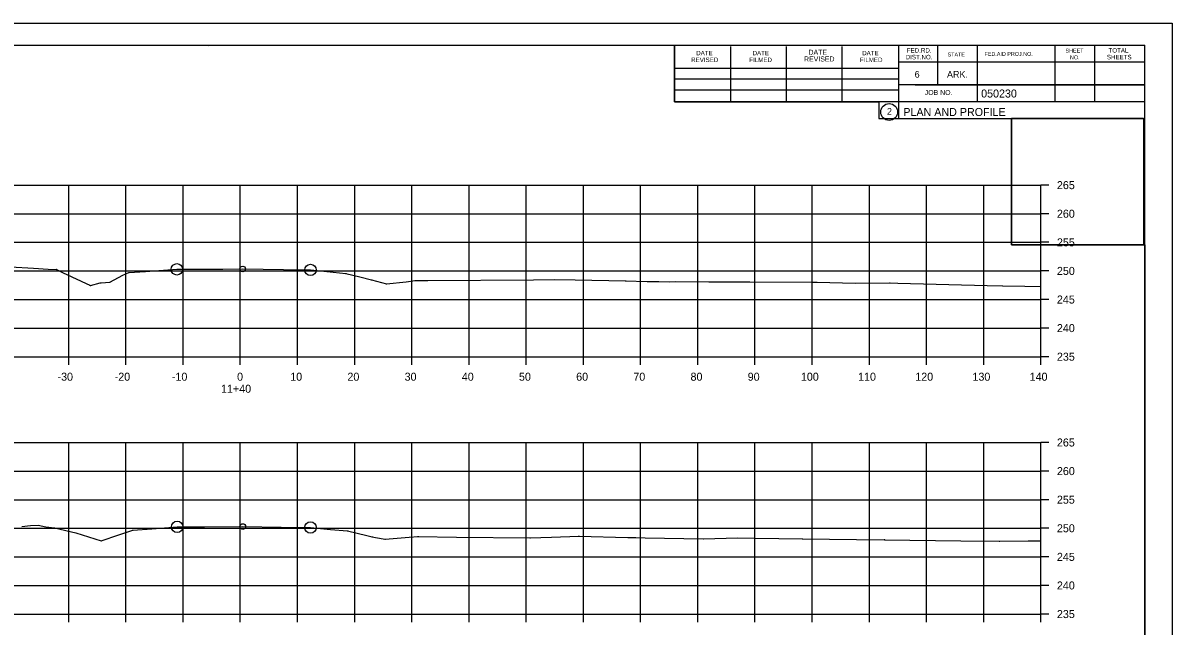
# Model space of a CAD drawing. Extents: x 1300404 to 1323571, y 234004 to 252077.
# Drawn here: x 1315679.3 to 1315880.2, y 243729.7 to 243835.2 of the extents above; entities that cross this region are included whole.
import ezdxf

# ---------------------------------------------------------------- set-up
doc = ezdxf.new("R2010")
doc.units = 0
for name, color, linetype in [('Default', 7, 'Continuous'), ('R_Axis', 7, 'Continuous'), ('R_Axis Annot', 7, 'Continuous'), ('R_Border', 7, 'Continuous'), ('R_Border Prem', 7, 'Continuous'), ('R_Draft', 7, 'Continuous'), ('R_Exist Surface', 7, 'Continuous'), ('R_Grid', 7, 'Continuous'), ('R_No Plot', 7, 'Continuous')]:
    doc.layers.add(name, color=color, linetype=linetype)

msp = doc.modelspace()

# ---------------------------------------------------------------- linework, layer by layer
at = {"layer": 'Default'}
for p, q in [((1315559.28, 243831.27), (1315875.46, 243831.27)), ((1315793.2, 243821.39), (1315793.2, 243831.27)), ((1315803.06, 243821.39), (1315803.06, 243831.07)), ((1315812.82, 243821.39), (1315812.82, 243831.07)), ((1315822.5, 243821.39), (1315822.5, 243831.07)), ((1315832.36, 243831.27), (1315832.36, 243818.47)), ((1315839.2, 243831.27), (1315839.2, 243824.33)), ((1315846.14, 243831.27), (1315846.14, 243821.39)), ((1315859.72, 243831.27), (1315859.72, 243821.39)), ((1315866.66, 243831.27), (1315866.66, 243821.39)), ((1315875.46, 243625.81), (1315875.46, 243831.27)), ((1315793.2, 243827.25), (1315832.36, 243827.25)), ((1315875.46, 243828.33), (1315832.36, 243828.33)), ((1315875.46, 243828.35), (1315875.46, 243828.35)), ((1315793.2, 243825.39), (1315832.36, 243825.39)), ((1315793.2, 243821.39), (1315793.2, 243823.45)), ((1315793.2, 243823.45), (1315832.36, 243823.45)), ((1315875.46, 243824.33), (1315832.36, 243824.33)), ((1315835.32, 243824.33), (1315875.46, 243824.33)), ((1315875.46, 243821.39), (1315793.2, 243821.39)), ((1315832.36, 243818.47), (1315875.46, 243818.47))]:
    msp.add_line(p, q, dxfattribs=at)
msp.add_circle((1315830.74, 243819.6), 1.47, dxfattribs=at)
at = {"layer": 'R_Axis'}
for p, q in [((1315857.28, 243776.81), (1315857.28, 243806.81)), ((1315858.68, 243806.81), (1315857.28, 243806.81)), ((1315858.68, 243801.81), (1315857.28, 243801.81)), ((1315858.68, 243796.81), (1315857.28, 243796.81)), ((1315858.68, 243791.81), (1315857.28, 243791.81)), ((1315858.68, 243786.81), (1315857.28, 243786.81)), ((1315858.68, 243781.81), (1315857.28, 243781.81)), ((1315577.28, 243776.81), (1315857.28, 243776.81)), ((1315687.28, 243775.41), (1315687.28, 243776.81)), ((1315697.28, 243775.41), (1315697.28, 243776.81)), ((1315707.28, 243775.41), (1315707.28, 243776.81)), ((1315717.28, 243775.41), (1315717.28, 243776.81)), ((1315727.28, 243775.41), (1315727.28, 243776.81)), ((1315737.28, 243775.41), (1315737.28, 243776.81)), ((1315747.28, 243775.41), (1315747.28, 243776.81)), ((1315757.28, 243775.41), (1315757.28, 243776.81)), ((1315767.28, 243775.41), (1315767.28, 243776.81)), ((1315777.28, 243775.41), (1315777.28, 243776.81)), ((1315787.28, 243775.41), (1315787.28, 243776.81)), ((1315797.28, 243775.41), (1315797.28, 243776.81)), ((1315807.28, 243775.41), (1315807.28, 243776.81)), ((1315817.28, 243775.41), (1315817.28, 243776.81)), ((1315827.28, 243775.41), (1315827.28, 243776.81)), ((1315837.28, 243775.41), (1315837.28, 243776.81)), ((1315847.28, 243775.41), (1315847.28, 243776.81)), ((1315857.28, 243775.41), (1315857.28, 243776.81)), ((1315858.68, 243776.81), (1315857.28, 243776.81)), ((1315857.28, 243731.81), (1315857.28, 243761.81)), ((1315858.68, 243761.81), (1315857.28, 243761.81)), ((1315858.68, 243756.81), (1315857.28, 243756.81)), ((1315858.68, 243751.81), (1315857.28, 243751.81)), ((1315858.68, 243746.81), (1315857.28, 243746.81)), ((1315858.68, 243741.81), (1315857.28, 243741.81)), ((1315858.68, 243736.81), (1315857.28, 243736.81)), ((1315577.28, 243731.81), (1315857.28, 243731.81)), ((1315687.28, 243730.41), (1315687.28, 243731.81)), ((1315697.28, 243730.41), (1315697.28, 243731.81)), ((1315707.28, 243730.41), (1315707.28, 243731.81)), ((1315717.28, 243730.41), (1315717.28, 243731.81)), ((1315727.28, 243730.41), (1315727.28, 243731.81)), ((1315737.28, 243730.41), (1315737.28, 243731.81)), ((1315747.28, 243730.41), (1315747.28, 243731.81)), ((1315757.28, 243730.41), (1315757.28, 243731.81)), ((1315767.28, 243730.41), (1315767.28, 243731.81)), ((1315777.28, 243730.41), (1315777.28, 243731.81)), ((1315787.28, 243730.41), (1315787.28, 243731.81)), ((1315797.28, 243730.41), (1315797.28, 243731.81)), ((1315807.28, 243730.41), (1315807.28, 243731.81)), ((1315817.28, 243730.41), (1315817.28, 243731.81)), ((1315827.28, 243730.41), (1315827.28, 243731.81)), ((1315837.28, 243730.41), (1315837.28, 243731.81)), ((1315847.28, 243730.41), (1315847.28, 243731.81)), ((1315857.28, 243730.41), (1315857.28, 243731.81)), ((1315858.68, 243731.81), (1315857.28, 243731.81))]:
    msp.add_line(p, q, dxfattribs=at)
at = {"layer": 'R_Border'}
msp.add_line((1315711.8, 243831.01), (1315711.8, 243831.01), dxfattribs=at)
msp.add_line((1315711.8, 243831.01), (1315711.8, 243831.01), dxfattribs=at)
at = {"layer": 'R_Draft'}
for points in [[(1315685.11, 243792.13), (1315685.16, 243792.03), (1315685.06, 243792.03)], [(1315697.77, 243791.56), (1315697.82, 243791.46), (1315697.72, 243791.46)], [(1315735.72, 243791.41), (1315735.77, 243791.31), (1315735.67, 243791.31)], [(1315691.07, 243789.3), (1315691.12, 243789.2), (1315691.02, 243789.2)], [(1315692.91, 243789.78), (1315692.96, 243789.68), (1315692.86, 243789.68)], [(1315694.46, 243789.87), (1315694.51, 243789.77), (1315694.41, 243789.77)], [(1315740.19, 243790.29), (1315740.24, 243790.19), (1315740.14, 243790.19)], [(1315742.85, 243789.62), (1315742.9, 243789.52), (1315742.8, 243789.52)], [(1315747.85, 243790.16), (1315747.9, 243790.06), (1315747.8, 243790.06)], [(1315784.64, 243790.13), (1315784.69, 243790.03), (1315784.59, 243790.03)], [(1315817.25, 243789.92), (1315817.3, 243789.82), (1315817.2, 243789.82)], [(1315830.88, 243789.75), (1315830.93, 243789.65), (1315830.83, 243789.65)], [(1315850.59, 243789.23), (1315850.64, 243789.13), (1315850.54, 243789.13)], [(1315684.81, 243746.91), (1315684.86, 243746.81), (1315684.76, 243746.81)], [(1315698.5, 243746.52), (1315698.55, 243746.42), (1315698.45, 243746.42)], [(1315692.97, 243744.66), (1315693.02, 243744.56), (1315692.92, 243744.56)], [(1315736.01, 243746.41), (1315736.06, 243746.31), (1315735.96, 243746.31)], [(1315740.34, 243745.38), (1315740.39, 243745.28), (1315740.29, 243745.28)], [(1315742.61, 243744.93), (1315742.66, 243744.83), (1315742.56, 243744.83)], [(1315748.39, 243745.41), (1315748.44, 243745.31), (1315748.34, 243745.31)], [(1315767.96, 243745.17), (1315768.01, 243745.07), (1315767.91, 243745.07)], [(1315776.48, 243745.47), (1315776.53, 243745.37), (1315776.43, 243745.37)], [(1315786.34, 243745.23), (1315786.39, 243745.13), (1315786.29, 243745.13)], [(1315798.24, 243745.03), (1315798.29, 243744.93), (1315798.19, 243744.93)], [(1315815.6, 243744.99), (1315815.65, 243744.89), (1315815.55, 243744.89)], [(1315829.93, 243744.86), (1315829.98, 243744.76), (1315829.88, 243744.76)], [(1315850.02, 243744.59), (1315850.07, 243744.49), (1315849.97, 243744.49)]]:
    msp.add_lwpolyline(points, close=True, dxfattribs=at)
at = {"layer": 'R_Exist Surface'}
for points in [[(1315673.02, 243792.77), (1315681.09, 243792.3), (1315683.68, 243792.14), (1315685.11, 243792.08), (1315686.16, 243791.52), (1315691.07, 243789.25), (1315692.79, 243789.71), (1315692.91, 243789.73), (1315692.93, 243789.73), (1315694.46, 243789.82), (1315696.74, 243791.06), (1315697.77, 243791.51), (1315700.72, 243791.71), (1315706.19, 243792.09), (1315714.22, 243792.13), (1315717.69, 243792.15), (1315724.82, 243792.04), (1315729.55, 243791.98), (1315731.3, 243791.81), (1315735.72, 243791.36), (1315738.15, 243790.78), (1315740.19, 243790.24), (1315741.97, 243789.8), (1315742.85, 243789.57), (1315746.29, 243789.93), (1315747.85, 243790.11), (1315748.23, 243790.13), (1315748.56, 243790.14), (1315750.08, 243790.13), (1315768.56, 243790.24), (1315772.19, 243790.31), (1315775.82, 243790.26), (1315784.64, 243790.08), (1315788.41, 243789.97), (1315789.57, 243789.96), (1315790.49, 243789.96), (1315792.4, 243789.91), (1315793.39, 243789.95), (1315799.22, 243789.9), (1315803.38, 243789.9), (1315803.41, 243789.9), (1315803.44, 243789.9), (1315806.37, 243789.89), (1315817.25, 243789.87), (1315818.16, 243789.85), (1315824.79, 243789.66), (1315830.88, 243789.7), (1315832.28, 243789.67), (1315847.91, 243789.28), (1315850.59, 243789.18), (1315854.47, 243789.13), (1315857.28, 243789.11)], [(1315679.09, 243747.14), (1315680.59, 243747.29), (1315681.94, 243747.33), (1315683.25, 243747.04), (1315684.81, 243746.86), (1315688.54, 243746.02), (1315692.97, 243744.61), (1315696.03, 243745.64), (1315698.5, 243746.47), (1315701.82, 243746.73), (1315706.23, 243747.05), (1315711.04, 243747.08), (1315717.71, 243747.1), (1315724.42, 243747.01), (1315729.55, 243746.94), (1315733.04, 243746.61), (1315736.01, 243746.36), (1315739.42, 243745.54), (1315740.34, 243745.33), (1315740.91, 243745.2), (1315742.61, 243744.88), (1315746.79, 243745.24), (1315748.39, 243745.36), (1315755.1, 243745.24), (1315767.96, 243745.12), (1315771.7, 243745.25), (1315776.48, 243745.42), (1315785.02, 243745.21), (1315786.34, 243745.18), (1315788.08, 243745.16), (1315798.24, 243744.98), (1315804.27, 243745.11), (1315807.33, 243745.09), (1315815.6, 243744.94), (1315825.02, 243744.87), (1315829.93, 243744.81), (1315843.27, 243744.62), (1315850.02, 243744.54), (1315855.03, 243744.59), (1315857.28, 243744.59)]]:
    msp.add_lwpolyline(points, dxfattribs=at)
at = {"layer": 'R_Grid'}
for p, q in [((1315577.28, 243806.81), (1315857.28, 243806.81)), ((1315687.28, 243776.81), (1315687.28, 243806.81)), ((1315697.28, 243776.81), (1315697.28, 243806.81)), ((1315707.28, 243776.81), (1315707.28, 243806.81)), ((1315717.28, 243776.81), (1315717.28, 243806.81)), ((1315727.28, 243776.81), (1315727.28, 243806.81)), ((1315737.28, 243776.81), (1315737.28, 243806.81)), ((1315747.28, 243776.81), (1315747.28, 243806.81)), ((1315757.28, 243776.81), (1315757.28, 243806.81)), ((1315767.28, 243776.81), (1315767.28, 243806.81)), ((1315777.28, 243776.81), (1315777.28, 243806.81)), ((1315787.28, 243776.81), (1315787.28, 243806.81)), ((1315797.28, 243776.81), (1315797.28, 243806.81)), ((1315807.28, 243776.81), (1315807.28, 243806.81)), ((1315817.28, 243776.81), (1315817.28, 243806.81)), ((1315827.28, 243776.81), (1315827.28, 243806.81)), ((1315837.28, 243776.81), (1315837.28, 243806.81)), ((1315847.28, 243776.81), (1315847.28, 243806.81)), ((1315857.28, 243776.81), (1315857.28, 243806.81)), ((1315577.28, 243801.81), (1315857.28, 243801.81)), ((1315577.28, 243796.81), (1315857.28, 243796.81)), ((1315577.28, 243791.81), (1315857.28, 243791.81)), ((1315577.28, 243786.81), (1315857.28, 243786.81)), ((1315577.28, 243781.81), (1315857.28, 243781.81)), ((1315577.28, 243776.81), (1315857.28, 243776.81)), ((1315577.28, 243761.81), (1315857.28, 243761.81)), ((1315687.28, 243731.81), (1315687.28, 243761.81)), ((1315697.28, 243731.81), (1315697.28, 243761.81)), ((1315707.28, 243731.81), (1315707.28, 243761.81)), ((1315717.28, 243731.81), (1315717.28, 243761.81)), ((1315727.28, 243731.81), (1315727.28, 243761.81)), ((1315737.28, 243731.81), (1315737.28, 243761.81)), ((1315747.28, 243731.81), (1315747.28, 243761.81)), ((1315757.28, 243731.81), (1315757.28, 243761.81)), ((1315767.28, 243731.81), (1315767.28, 243761.81)), ((1315777.28, 243731.81), (1315777.28, 243761.81)), ((1315787.28, 243731.81), (1315787.28, 243761.81)), ((1315797.28, 243731.81), (1315797.28, 243761.81)), ((1315807.28, 243731.81), (1315807.28, 243761.81)), ((1315817.28, 243731.81), (1315817.28, 243761.81)), ((1315827.28, 243731.81), (1315827.28, 243761.81)), ((1315837.28, 243731.81), (1315837.28, 243761.81)), ((1315847.28, 243731.81), (1315847.28, 243761.81)), ((1315857.28, 243731.81), (1315857.28, 243761.81)), ((1315577.28, 243756.81), (1315857.28, 243756.81)), ((1315577.28, 243751.81), (1315857.28, 243751.81)), ((1315577.28, 243746.81), (1315857.28, 243746.81)), ((1315577.28, 243741.81), (1315857.28, 243741.81)), ((1315577.28, 243736.81), (1315857.28, 243736.81)), ((1315577.28, 243731.81), (1315857.28, 243731.81))]:
    msp.add_line(p, q, dxfattribs=at)
at = {"layer": 'R_No Plot'}
msp.add_line((1315546.87, 243835.16), (1315880.21, 243835.16), dxfattribs=at)
for points in [[(1315546.87, 243835.16), (1315880.21, 243835.16), (1315880.21, 243621.83), (1315546.87, 243621.83)], [(1315793.2, 243831.27), (1315793.2, 243821.39), (1315828.93, 243821.39), (1315828.93, 243818.47), (1315852.13, 243818.47), (1315852.13, 243796.35), (1315875.46, 243796.35), (1315875.46, 243625.81), (1315559.28, 243625.81), (1315559.28, 243831.27)], [(1315852.13, 243818.5), (1315875.23, 243818.5), (1315875.23, 243796.35), (1315852.13, 243796.35)]]:
    msp.add_lwpolyline(points, close=True, dxfattribs=at)
for centre, radius in [((1315706.19, 243792.09), 1), ((1315729.55, 243791.98), 1), ((1315717.69, 243792.15), 0.5), ((1315706.23, 243747.05), 1), ((1315717.71, 243747.1), 0.5), ((1315729.55, 243746.94), 1)]:
    msp.add_circle(centre, radius, dxfattribs=at)

# ---------------------------------------------------------------- texts
at = {"layer": 'Default'}
msp.add_text('2', height=1.17, dxfattribs=at).set_placement((1315830.36, 243819.12))
at = {"layer": 'R_Axis Annot'}
for s, p in [('265', (1315860.08, 243806.11)), ('260', (1315860.08, 243801.11)), ('255', (1315860.08, 243796.11)), ('250', (1315860.08, 243791.11)), ('245', (1315860.08, 243786.11)), ('240', (1315860.08, 243781.11)), ('235', (1315860.08, 243776.11)), ('-30', (1315685.31, 243772.61)), ('-20', (1315695.31, 243772.61)), ('-10', (1315705.31, 243772.61)), ('0', (1315716.71, 243772.61)), ('10', (1315726.01, 243772.61)), ('20', (1315736.01, 243772.61)), ('30', (1315746.01, 243772.61)), ('40', (1315756.01, 243772.61)), ('50', (1315766.01, 243772.61)), ('60', (1315776.01, 243772.61)), ('70', (1315786.01, 243772.61)), ('80', (1315796.01, 243772.61)), ('90', (1315806.01, 243772.61)), ('100', (1315815.31, 243772.61)), ('110', (1315825.31, 243772.61)), ('120', (1315835.31, 243772.61)), ('130', (1315845.31, 243772.61)), ('140', (1315855.31, 243772.61)), ('11+40', (1315713.91, 243770.51)), ('265', (1315860.08, 243761.11)), ('260', (1315860.08, 243756.11)), ('255', (1315860.08, 243751.11)), ('250', (1315860.08, 243746.11)), ('245', (1315860.08, 243741.11)), ('240', (1315860.08, 243736.11)), ('235', (1315860.08, 243731.11))]:
    msp.add_text(s, height=1.4, dxfattribs=at).set_placement(p)
at = {"layer": 'R_Border'}
for s, height, p in [('REVISED', 0.782, (1315796.12, 243828.33)), ('DATE', 0.782, (1315797, 243829.51)), ('FILMED', 0.782, (1315806.28, 243828.33)), ('DATE', 0.782, (1315806.86, 243829.51)), ('REVISED', 0.879, (1315815.86, 243828.43)), ('DATE', 0.879, (1315816.64, 243829.61)), ('FILMED', 0.782, (1315825.62, 243828.33)), ('DATE', 0.782, (1315826.02, 243829.51)), ('DIST.NO.', 0.782, (1315833.64, 243828.81)), ('FED.RD.', 0.782, (1315833.84, 243829.99)), ('STATE', 0.684, (1315840.96, 243829.31)), ('FED.AID PROJ.NO.', 0.684, (1315847.42, 243829.41)), ('SHEET', 0.684, (1315861.58, 243829.99)), ('NO.', 0.684, (1315862.36, 243828.81)), ('SHEETS', 0.782, (1315868.82, 243828.81)), ('TOTAL', 0.782, (1315869.1, 243829.99)), ('6', 1.17, (1315835.2, 243825.59)), ('ARK.', 1.172, (1315840.86, 243825.59)), ('JOB NO.', 0.879, (1315836.96, 243822.57))]:
    msp.add_text(s, height=height, dxfattribs=at).set_placement(p)
for s, p in [('050230', (1315846.83, 243822.13)), ('PLAN AND PROFILE', (1315833.22, 243818.9))]:
    msp.add_text(s, height=1.4, rotation=360, dxfattribs=at).set_placement(p)
at = {"layer": 'R_Border Prem'}
msp.add_text('DWB', height=0.01, dxfattribs=at).set_placement((1315836.15, 243812.78))

doc.saveas('drawing.dxf')
